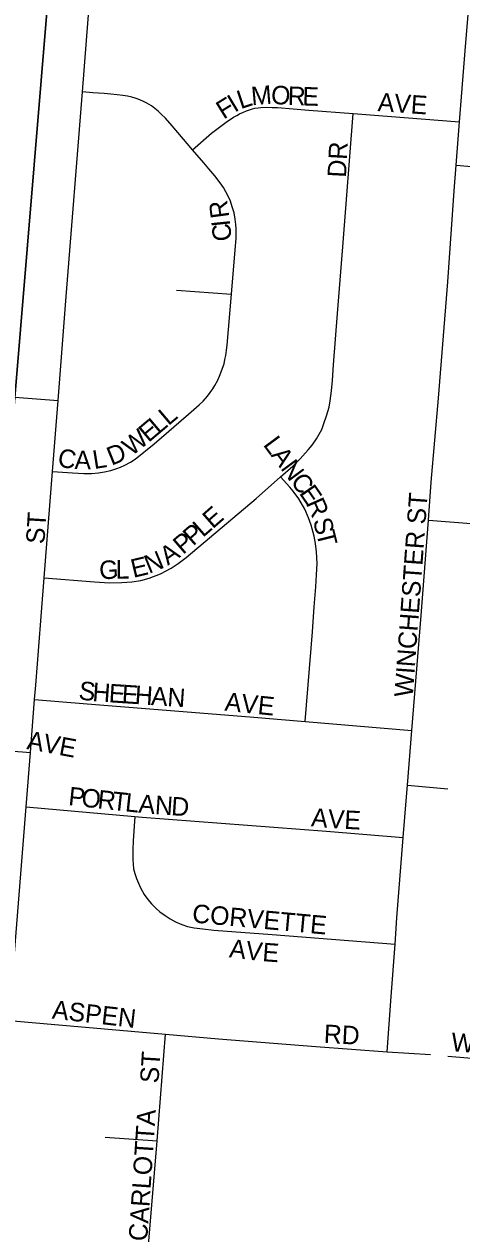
# Model space of a CAD drawing. Extents: x 1410790 to 1770854, y 566777 to 831614.
# Drawn here: x 1538845 to 1540024, y 687949 to 691186 of the extents above; entities that cross this region are included whole.
import ezdxf

# ---------------------------------------------------------------- set-up
doc = ezdxf.new("R2010")
doc.units = 0
for name, color, linetype in [('GM_X_Section', 7, 'Continuous'), ('GM_X_Township_Subdivision', 7, 'Continuous'), ('GM_X_Township_Subdivision_Text', 7, 'Continuous')]:
    doc.layers.add(name, color=color, linetype=linetype)

msp = doc.modelspace()

# ---------------------------------------------------------------- linework, layer by layer
at = {"layer": 'GM_X_Section'}
for points in [[(1533714, 693688.2), (1533718.7, 693734.1), (1539075.1, 693257.5), (1538630.6, 687908.5), (1533250.7, 688399.5)], [(1539075.1, 693257.5), (1544412, 692697.3), (1543934.6, 687408.9), (1538798.3, 687891.7), (1538630.6, 687908.5)]]:
    msp.add_lwpolyline(points, close=True, dxfattribs=at)
at = {"layer": 'GM_X_Township_Subdivision'}
for points in [[(1539002.4, 691002.4), (1539024.3, 691280.7), (1539025.1, 691290.9)], [(1540020.6, 690920.8), (1540035.8, 691113), (1540043.8, 691211)], [(1538936.6, 690168.4), (1538958.8, 690449), (1539002.4, 691002.4)], [(1539299.7, 690845.6), (1539284.9, 690862.8), (1539244.4, 690910), (1539226.4, 690930.7), (1539215.3, 690942.2), (1539206.5, 690950.3), (1539197.9, 690957.3), (1539189, 690964.1), (1539176.5, 690971.5), (1539165.6, 690976.9), (1539152.8, 690982.1), (1539144.7, 690985), (1539135.4, 690987.6), (1539123.8, 690990.2), (1539111.2, 690992.2), (1539095.9, 690994.5), (1539079.2, 690996), (1539061.4, 690997.5), (1539030.6, 690999.7), (1539002.4, 691002.4)], [(1539299.7, 690845.6), (1539351.2, 690890.5), (1539390.8, 690920.2), (1539410, 690933.4), (1539418.8, 690938.4), (1539426.2, 690942.5), (1539437.2, 690947.5), (1539445.4, 690951), (1539453.6, 690953.9), (1539461.8, 690956.4), (1539468.2, 690957.8), (1539476.8, 690959.3), (1539484.3, 690960), (1539498.6, 690960.7), (1539514.3, 690960.3), (1539529.3, 690959.6), (1539613.5, 690952.9), (1539733, 690943.4)], [(1539537.5, 689962.3), (1539570.1, 689991), (1539590.5, 690011.1), (1539611.8, 690035.3), (1539622.4, 690047.7), (1539634.3, 690064.5), (1539648.3, 690089.8), (1539654.3, 690106.6), (1539661.3, 690126.8), (1539668.6, 690150.8), (1539671.5, 690167.6), (1539675, 690194.3), (1539677.2, 690222.4), (1539680.6, 690264.4), (1539691, 690403.3), (1539705.2, 690583.8), (1539733, 690943.4)], [(1539733, 690943.4), (1540020.6, 690920.8)], [(1540011.4, 690803.7), (1540020.6, 690920.8)], [(1539404.4, 690455.5), (1539414.6, 690575.6), (1539417, 690605.6), (1539417.7, 690622.1), (1539417.7, 690631.8), (1539416.9, 690643.5), (1539414.9, 690658.7), (1539411.6, 690675.6), (1539407, 690691.7), (1539401.9, 690706.8), (1539396, 690720.8), (1539389.7, 690732.4), (1539383.2, 690743.4), (1539373.9, 690756.2), (1539359.4, 690775.1), (1539343.6, 690794.5), (1539329.9, 690810.5), (1539299.7, 690845.6)], [(1539936.3, 689845.5), (1539943.8, 689947.5), (1539963.6, 690174.8), (1539988.5, 690489.1), (1540006.3, 690734.4), (1540011.4, 690803.7)], [(1540011.4, 690803.7), (1540136.7, 690793.6)], [(1538921.7, 689977.1), (1538975.7, 689973.5), (1539005.9, 689971.7), (1539026.5, 689971.7), (1539046.2, 689972.9), (1539062.1, 689975.4), (1539079.3, 689979.6), (1539095.6, 689984.6), (1539105.6, 689988.4), (1539117.2, 689993.7), (1539132.4, 690002.2), (1539145.2, 690010.4), (1539196.2, 690051.4), (1539288.9, 690131.6), (1539317.3, 690156.5), (1539328.1, 690166.9), (1539339.8, 690180.3), (1539347.4, 690190), (1539354.5, 690200), (1539360, 690209.3), (1539367.5, 690223.4), (1539374.3, 690238.7), (1539380.8, 690255.7), (1539384.6, 690267.8), (1539387, 690278.8), (1539389.1, 690289.8), (1539391, 690304.1), (1539392.7, 690318), (1539404.4, 690455.5)], [(1539256.4, 690466.8), (1539404.4, 690455.5)], [(1538639.3, 690190.9), (1538703.1, 690186.3), (1538936.6, 690168.4)], [(1538921.7, 689977.1), (1538936.6, 690168.4)], [(1538899.1, 689689.5), (1538921.7, 689977.1)], [(1538899.1, 689689.5), (1539035.3, 689678.3), (1539075.4, 689676), (1539109.1, 689676.7), (1539135.7, 689678.8), (1539160.2, 689682.3), (1539182.5, 689689), (1539213.2, 689700.7), (1539242.4, 689715.9), (1539260.5, 689727.9), (1539282.7, 689744.5), (1539471.3, 689904), (1539537.5, 689962.3)], [(1539603.4, 689301.5), (1539623.2, 689543.6), (1539628, 689610.8), (1539632.1, 689664.9), (1539634.4, 689697.2), (1539635.7, 689728.6), (1539634.3, 689759.5), (1539631.5, 689781.9), (1539628, 689801.6), (1539619.6, 689831.7), (1539612.6, 689851.3), (1539602.7, 689875.2), (1539586.6, 689902.6), (1539571.2, 689923.6), (1539562.2, 689934.8), (1539537.5, 689962.3)], [(1539891.9, 689277), (1539917, 689588.1), (1539936.3, 689845.5)], [(1539936.3, 689845.5), (1540063.3, 689835.2)], [(1538873.2, 689360.5), (1538876.3, 689399.8), (1538899.1, 689689.5)], [(1538861.9, 689218.1), (1538873.2, 689360.5)], [(1538873.2, 689360.5), (1539015.2, 689348.9), (1539454.3, 689314.5), (1539603.4, 689301.5)], [(1539603.4, 689301.5), (1539891.9, 689277)], [(1539880, 689129.2), (1539891.9, 689277)], [(1538568.3, 689239.6), (1538840.2, 689219.7), (1538861.9, 689218.1)], [(1538850.3, 689070.8), (1538861.9, 689218.1)], [(1539868.6, 688988.2), (1539877.4, 689098), (1539880, 689129.2)], [(1539880, 689129.2), (1539989, 689119.6)], [(1538804.6, 688493.5), (1538850.3, 689070.8)], [(1538850.3, 689070.8), (1539144.2, 689045.1)], [(1539144.2, 689045.1), (1539139.5, 688979.4), (1539138.3, 688955.9), (1539138.3, 688929.1), (1539139.1, 688916.1), (1539140.7, 688903.9), (1539143.5, 688890.5), (1539148, 688877.1), (1539159.2, 688852), (1539169.5, 688834.5), (1539179.3, 688820.6), (1539188.9, 688809.1), (1539200.7, 688796.9), (1539211.8, 688787.6), (1539225.9, 688777.2), (1539239.4, 688768.2), (1539254.1, 688760), (1539270.6, 688752.8), (1539286.3, 688747.8), (1539304.2, 688744.1), (1539327, 688741.2), (1539357.1, 688738.1), (1539514.2, 688726.5), (1539846.4, 688700.4)], [(1539144.2, 689045.1), (1539163.6, 689043.4), (1539660.9, 689005.2), (1539868.6, 688988.2)], [(1539846.4, 688700.4), (1539851.4, 688771.2), (1539868.6, 688988.2)], [(1539825.3, 688409.5), (1539836.3, 688558.9), (1539846.4, 688700.4)], [(1538804.6, 688493.5), (1539226.4, 688456.9)], [(1539204, 688169.2), (1539226.4, 688456.9)], [(1539226.4, 688456.9), (1539369.6, 688444.5), (1539632.1, 688423.8), (1539825.3, 688409.5)], [(1539825.3, 688409.5), (1539941.8, 688401.6)], [(1539988.8, 688397.1), (1540139.2, 688384.8), (1540268, 688375.6), (1540418.6, 688363.7), (1540514.1, 688356.3), (1540641.8, 688346.2)], [(1539063.7, 688178.9), (1539204, 688169.2)], [(1539178.9, 687858.1), (1539181.2, 687886.6), (1539204, 688169.2)]]:
    msp.add_lwpolyline(points, dxfattribs=at)

# ---------------------------------------------------------------- texts
at = {"layer": 'GM_X_Township_Subdivision_Text'}
for s, rotation, p in [('F', 31.7766, (1539383.5, 690926.6)), ('I', 31.0462, (1539413.2, 690945.1)), ('L', 18.2578, (1539429.4, 690955.2)), ('M', 4.8597, (1539459.8, 690965.6)), ('O', 356.1612, (1539510.4, 690970.1)), ('R', 357.9029, (1539556, 690967)), ('E', 358.0963, (1539595.7, 690965.6)), ('AVE', 356.0534, (1539798.5, 690950.2)), ('DR', 86.983, (1539713.7, 690769.7)), ('R', 97.7187, (1539399.1, 690664)), ('I', 95.9346, (1539401.6, 690640.5)), ('C', 95.9486, (1539405.7, 690601.1)), ('E', 40.2134, (1539180.8, 690053.5)), ('L', 40.1938, (1539207.7, 690076.2)), ('L', 40.1959, (1539234.6, 690098.9)), ('W', 38.9953, (1539135.4, 690016.7)), ('D', 22.0906, (1539080.9, 689992)), ('L', 306.5667, (1539488.6, 690048.8)), ('C', 350.1904, (1538933.2, 689990.7)), ('A', 359.1145, (1538980.7, 689983.2)), ('L', 8.9975, (1539034.1, 689983.2)), ('A', 306.5617, (1539509.6, 690020.5)), ('N', 306.562, (1539535.8, 689985.1)), ('C', 307.1679, (1539562.3, 689949.4)), ('E', 304.7055, (1539585.9, 689918.3)), ('R', 294.05, (1539604.8, 689891.5)), ('WINCHESTER ST', 85.803, (1539894, 689365.9)), ('ST', 86.4258, (1538899.7, 689779.8)), ('E', 41.1821, (1539354, 689820.2)), ('P', 41.1897, (1539301, 689773.8)), ('L', 41.1821, (1539327.5, 689797)), ('S', 285.0898, (1539624, 689844.6)), ('P', 40.7153, (1539274, 689750.6)), ('T', 283.9468, (1539633.1, 689810.9)), ('N', 22.2518, (1539182, 689699.9)), ('A', 34.3768, (1539232.9, 689722)), ('G', 2.9192, (1539048.9, 689685.2)), ('L', 0.4508, (1539092.3, 689687.4)), ('E', 13.4588, (1539139.8, 689689.2)), ('S', 352.6581, (1538990.3, 689361.6)), ('H', 355.8265, (1539028.2, 689356.8)), ('E', 356.1773, (1539072.4, 689353.5)), ('E', 356.1859, (1539107.5, 689351.2)), ('H', 356.1815, (1539142.7, 689348.9)), ('A', 356.1869, (1539186.6, 689345.9)), ('N', 356.183, (1539230.5, 689343)), ('AVE', 354.0932, (1539385.2, 689330.9)), ('A', 349.8603, (1538850.3, 689227.4)), ('V', 349.3716, (1538893.5, 689219.7)), ('E', 349.3836, (1538936.8, 689211.6)), ('P', 353.8137, (1538962.9, 689075.7)), ('O', 353.8135, (1538997.9, 689071.9)), ('R', 353.8177, (1539041.6, 689067.2)), ('T', 353.8001, (1539081, 689062.9)), ('L', 353.9055, (1539116.1, 689059.1)), ('A', 355.2745, (1539152.4, 689055.2)), ('N', 356.0294, (1539196.9, 689051.6)), ('D', 356.0519, (1539240.8, 689048.5)), ('A', 354.7472, (1539618.5, 689018.5)), ('V', 356.5757, (1539664, 689014.4)), ('E', 356.9863, (1539708.4, 689011.7)), ('CORVETTE', 354.8053, (1539297.3, 688758.9)), ('A', 353.1759, (1539397.1, 688664.7)), ('V', 353.5312, (1539441.2, 688659.4)), ('E', 355.7277, (1539487, 688654.3)), ('ASPEN', 353.5154, (1538918.9, 688499.3)), ('RD', 356.9887, (1539653.1, 688433.4)), ('W', 355.6039, (1539996.6, 688411.3)), ('ST', 86.4254, (1539207.7, 688323.4)), ('CARLOTTA', 86.1853, (1539176.9, 687896.6))]:
    msp.add_text(s, height=50, rotation=rotation, dxfattribs=at).set_placement(p)

doc.saveas('drawing.dxf')
